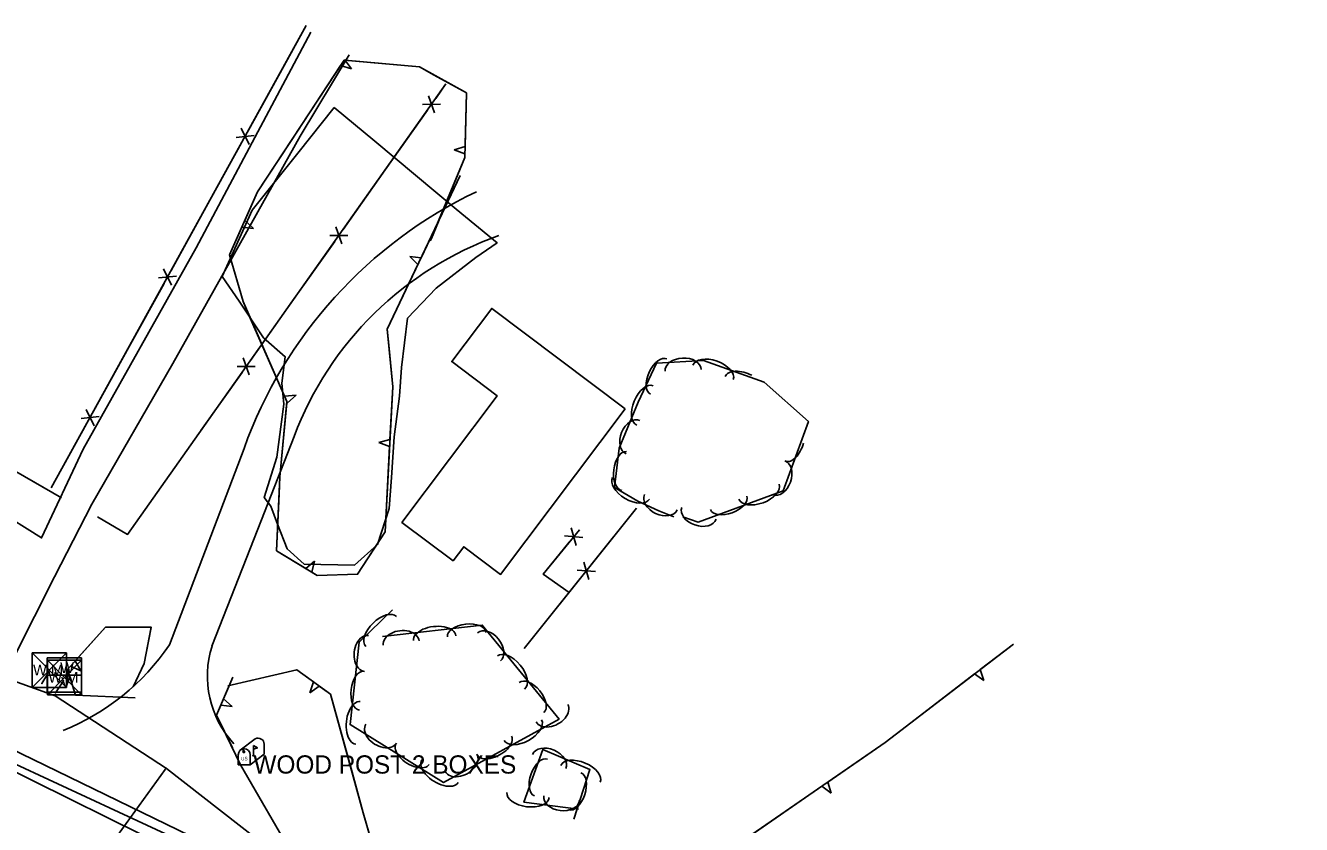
# Model space of a CAD drawing. Extents: x 954793 to 988390, y 1867850 to 1924428.
# Drawn here: x 964423.2 to 964773.1, y 1900700.5 to 1900919.5 of the extents above; entities that cross this region are included whole.
import ezdxf

# ---------------------------------------------------------------- set-up
doc = ezdxf.new("R2010")
doc.units = 0
for name, color, linetype in [('S_BUILDING', 7, 'Continuous'), ('S_DRIVEWAY', 7, 'Continuous'), ('S_FENCE', 7, 'Continuous'), ('S_FIBER_OPTIC_CABLE', 7, 'Continuous'), ('S_MAILBOX', 7, 'Continuous'), ('S_MAILBOX_ANNOT', 7, 'Continuous'), ('S_OBSCURES', 7, 'Continuous'), ('S_TREE', 7, 'Continuous'), ('S_UTL_PT_SYM', 7, 'Continuous'), ('S_WATER_UTILITIES', 7, 'Continuous')]:
    doc.layers.add(name, color=color, linetype=linetype)

msp = doc.modelspace()

# ---------------------------------------------------------------- linework, layer by layer
at = {"layer": 'S_BUILDING'}
msp.add_lwpolyline([(964587.61, 1900814.47), (964553.46, 1900769.08), (964543.35, 1900776.68), (964540.44, 1900772.82), (964526.43, 1900783.35), (964552.53, 1900818.04), (964540.07, 1900827.42), (964551.03, 1900841.99)], close=True, dxfattribs=at)
at = {"layer": 'S_DRIVEWAY'}
for points in [[(964501.46, 1900917.73), (964470.02, 1900858.62), (964439.06, 1900803.44), (964427.61, 1900779.09), (964415.01, 1900786.98), (964408.03, 1900790.26)], [(964414.54, 1900735.61), (964431.15, 1900768.41), (964441.36, 1900788.36), (964463.61, 1900826.91), (964479.18, 1900854.57), (964498.54, 1900889.19), (964511.97, 1900911.54)], [(964474.34, 1900749.37), (964486.93, 1900781.52), (964496.87, 1900806.92)], [(964483.13, 1900803.59), (964462.65, 1900749.74)]]:
    msp.add_lwpolyline(points, dxfattribs=at)
for centre, major_axis, ratio, start_param, end_param in [((964600.34, 1900761.56), (-97.01, -78.14), 0.999418, 4.478485, 5.260538), ((964583.94, 1900774.15), (-41.46, -83.42), 0.99866, 3.94198, 4.813547), ((964411.01, 1900784.53), (42.58, 46.67), 0.985265, 4.255726, 4.857047), ((964499.54, 1900740.8), (11.8, -24.14), 0.981329, 3.938934, 5.008652)]:
    msp.add_ellipse(centre, major_axis=major_axis, ratio=ratio, start_param=start_param, end_param=end_param, dxfattribs=at)
at = {"layer": 'S_FENCE'}
for p, q in [((964532.06, 1900897.93), (964537.03, 1900897.94)), ((964535.37, 1900895.59), (964533.72, 1900900.27)), ((964484.52, 1900886.89), (964482.31, 1900891.38)), ((964480.93, 1900888.87), (964485.9, 1900889.4)), ((964509.97, 1900859.67), (964508.32, 1900864.34)), ((964506.66, 1900862), (964511.63, 1900862.01)), ((964463.26, 1900848.36), (964461.06, 1900852.85)), ((964459.68, 1900850.34), (964464.65, 1900850.87)), ((964484.57, 1900823.74), (964482.91, 1900828.42)), ((964481.26, 1900826.07), (964486.22, 1900826.08)), ((964442.01, 1900809.83), (964439.81, 1900814.32)), ((964438.43, 1900811.81), (964443.4, 1900812.34)), ((964571.01, 1900779.61), (964575.99, 1900779.24)), ((964574.18, 1900777.02), (964572.82, 1900781.83)), ((964576.26, 1900772.47), (964577.67, 1900767.68)), ((964579.46, 1900769.92), (964574.47, 1900770.23))]:
    msp.add_line(p, q, dxfattribs=at)
for points in [[(964430.29, 1900792.81), (964500.18, 1900919.53)], [(964494.04, 1900908.4), (964500.18, 1900919.53)], [(964484.38, 1900890.89), (964494.04, 1900908.4)], [(964442.95, 1900784.84), (964451.2, 1900780.05), (964538.5, 1900903.52)], [(964535.7, 1900899.57), (964538.5, 1900903.52)], [(964521.84, 1900879.97), (964533.39, 1900896.3)], [(964472.79, 1900869.87), (964482.45, 1900887.39)], [(964510.3, 1900863.64), (964521.84, 1900879.97)], [(964463.13, 1900852.36), (964472.79, 1900869.87)], [(964496.44, 1900844.04), (964507.99, 1900860.37)], [(964451.54, 1900831.34), (964461.2, 1900848.85)], [(964484.89, 1900827.71), (964496.44, 1900844.04)], [(964441.88, 1900813.83), (964451.54, 1900831.34)], [(964471.31, 1900808.49), (964482.58, 1900824.44)], [(964430.29, 1900792.81), (964439.95, 1900810.32)], [(964433.12, 1900790.1), (964415.1, 1900800.42), (964399.59, 1900781.83)], [(964433.12, 1900790.1), (964415.76, 1900800.04)], [(964590.69, 1900787.27), (964559.96, 1900748.76)], [(964590.69, 1900787.27), (964578.21, 1900771.64)], [(964442.95, 1900784.84), (964445.41, 1900783.41)], [(964572.24, 1900764.09), (964565.11, 1900769.18), (964575.06, 1900781.33)], [(964574.77, 1900780.97), (964575.06, 1900781.33)], [(964572.24, 1900764.09), (964565.11, 1900769.18), (964572.23, 1900777.88)], [(964575.72, 1900768.51), (964563.25, 1900752.87)], [(964563.25, 1900752.87), (964559.96, 1900748.76)]]:
    msp.add_lwpolyline(points, dxfattribs=at)
at = {"layer": 'S_FIBER_OPTIC_CABLE'}
for p, q in [((964482.14, 1900690.77), (964389.31, 1900735.85)), ((964481.04, 1900688.98), (964388.89, 1900731.66)), ((964475.57, 1900687.67), (964389.43, 1900730.27))]:
    msp.add_line(p, q, dxfattribs=at)
at = {"layer": 'S_MAILBOX'}
for p, q in [((964482.08, 1900720.9), (964486.22, 1900724.01)), ((964488.65, 1900722.54), (964488.65, 1900719.82)), ((964481.53, 1900719.63), (964481.53, 1900716.91)), ((964484.85, 1900716.91), (964488.65, 1900719.82)), ((964484.85, 1900719.63), (964484.85, 1900716.91)), ((964485.7, 1900722.19), (964485.7, 1900719.48)), ((964481.53, 1900716.91), (964484.85, 1900716.91))]:
    msp.add_line(p, q, dxfattribs=at)
for points in [[(964482.71, 1900720.74), (964482.93, 1900720.61), (964482.93, 1900720.22), (964483.24, 1900720.22), (964483.24, 1900720.58), (964483.04, 1900720.83), (964482.71, 1900720.77)], [(964485.7, 1900722.19), (964486.81, 1900721.53), (964485.7, 1900721.18)]]:
    msp.add_lwpolyline(points, dxfattribs=at)
for centre, end in [((964486.99, 1900722.54), 117.5718), ((964483.19, 1900719.63), 180)]:
    msp.add_arc(centre, 1.66, 0, end, dxfattribs=at)
msp.add_ellipse((964485.7, 1900719.48), major_axis=(0.145, 0.132), ratio=0.564646, dxfattribs=at)
at = {"layer": 'S_OBSCURES'}
msp.add_lwpolyline([(964507.86, 1900897.07), (964497.9, 1900884.58), (964485.37, 1900868.89), (964477.09, 1900850.7), (964481.77, 1900843.97), (964488.49, 1900833.92), (964494.43, 1900828.74), (964493.48, 1900821.53), (964494.08, 1900815.77), (964492.14, 1900801.18), (964488.67, 1900790.19), (964490.5, 1900787.8), (964492.28, 1900782.82), (964494.97, 1900776.09), (964499.59, 1900771.89), (964513.39, 1900771.64), (964519.72, 1900777.27), (964522.91, 1900787.18), (964523.54, 1900795.6), (964524.26, 1900806.8), (964525.77, 1900817.94), (964526.32, 1900825.82), (964527.97, 1900839.35), (964535.83, 1900847.56), (964546.66, 1900855.91), (964552.49, 1900859.97), (964541.33, 1900869.24), (964530.17, 1900878.52), (964519.02, 1900887.79)], close=True, dxfattribs=at)
at = {"layer": 'S_TREE'}
for p, q in [((964509.59, 1900908.54), (964512.62, 1900907.68)), ((964512.62, 1900907.68), (964510.67, 1900910.18)), ((964543.72, 1900886.35), (964540.7, 1900885.48)), ((964540.7, 1900885.48), (964543.67, 1900884.38)), ((964485.68, 1900863.93), (964483.36, 1900866.08)), ((964482.56, 1900864.29), (964485.68, 1900863.93)), ((964531.66, 1900855.82), (964528.55, 1900856.25)), ((964528.55, 1900856.25), (964530.82, 1900854.05)), ((964497.4, 1900818.17), (964494.24, 1900817.9)), ((964495.03, 1900816.1), (964497.4, 1900818.17)), ((964523.13, 1900806.06), (964520.09, 1900805.28)), ((964520.09, 1900805.28), (964523.03, 1900804.1)), ((964502.47, 1900772.75), (964500.05, 1900770.71)), ((964501.73, 1900769.69), (964502.47, 1900772.75)), ((964435.54, 1900743.96), (964438.4, 1900742.65)), ((964438.4, 1900742.65), (964436.86, 1900745.42)), ((964683.42, 1900741.8), (964686, 1900740)), ((964686, 1900740), (964684.98, 1900743)), ((964502.14, 1900739.63), (964501.15, 1900736.65)), ((964501.15, 1900736.65), (964503.74, 1900738.48)), ((964476.75, 1900733.2), (964479.88, 1900732.88)), ((964479.88, 1900732.88), (964477.53, 1900735)), ((964644.06, 1900709.08), (964643.19, 1900712.13)), ((964641.58, 1900711.01), (964644.06, 1900709.08))]:
    msp.add_line(p, q, dxfattribs=at)
for points in [[(964542.37, 1900878.39), (964522.39, 1900836.28), (964523.9, 1900820.54), (964521.79, 1900780.75), (964514.25, 1900769.14), (964503.21, 1900768.8), (964492.04, 1900775.55), (964492.94, 1900795.85), (964494.87, 1900816.48), (964482.86, 1900843.88), (964479.18, 1900856.68), (964486.84, 1900873.91), (964510.59, 1900910.05), (964531.22, 1900908.17), (964544.11, 1900901.07), (964543.64, 1900883.35), (964534.19, 1900860.47)], [(964495.86, 1900887.65), (964509.59, 1900908.54)], [(964510.74, 1900910.04), (964531.22, 1900908.17), (964535.1, 1900906.03)], [(964535.1, 1900906.03), (964544.11, 1900901.07), (964543.72, 1900886.35)], [(964483.36, 1900866.08), (964486.84, 1900873.91), (964495.86, 1900887.65)], [(964543.67, 1900884.38), (964543.64, 1900883.35), (964534.49, 1900861.2)], [(964542.37, 1900878.39), (964531.66, 1900855.82)], [(964484.2, 1900840.8), (964482.86, 1900843.88), (964479.18, 1900856.68), (964482.56, 1900864.29)], [(964534.49, 1900861.2), (964534.19, 1900860.47)], [(964530.82, 1900854.05), (964522.39, 1900836.28), (964522.9, 1900830.99)], [(964494.24, 1900817.9), (964484.2, 1900840.8)], [(964522.9, 1900830.99), (964523.9, 1900820.54), (964523.13, 1900806.06)], [(964601, 1900784.82), (964596.85, 1900786.49), (964591.07, 1900789.17), (964584.66, 1900792.91), (964585.98, 1900803.7), (964591.16, 1900816.26), (964596.22, 1900827.02), (964609.1, 1900827.67), (964625.73, 1900821.77), (964637.85, 1900810.97), (964630.99, 1900791.96), (964607.67, 1900783.37), (964603.47, 1900784.82)], [(964492.74, 1900791.16), (964492.94, 1900795.85), (964494.83, 1900816.07)], [(964523.03, 1900804.1), (964521.79, 1900780.75), (964520.91, 1900779.39)], [(964500.05, 1900770.71), (964492.04, 1900775.55), (964492.74, 1900791.16)], [(964520.91, 1900779.39), (964514.25, 1900769.14), (964503.21, 1900768.8), (964501.73, 1900769.69)], [(964521.05, 1900752.08), (964548.46, 1900755.19), (964569.52, 1900729.42), (964537.78, 1900712.04), (964512.2, 1900727.93), (964514.65, 1900750.47), (964523.79, 1900759.35)], [(964453.28, 1900735.24), (964436.96, 1900735.97), (964434.71, 1900743.04), (964445.18, 1900754.63), (964457.69, 1900754.6), (964455.74, 1900744.64), (964452.75, 1900738.28)], [(964436.86, 1900745.42), (964445.18, 1900754.63), (964457.69, 1900754.6), (964457.68, 1900754.53)], [(964457.68, 1900754.53), (964455.74, 1900744.64), (964452.75, 1900738.28)], [(964773.05, 1900666.58), (964744.57, 1900646.52), (964725.6, 1900649.05), (964710.57, 1900666.38), (964700.3, 1900676.13), (964691.03, 1900680.68), (964665.4, 1900668.82), (964619.49, 1900640.89), (964600.99, 1900650.38), (964604.11, 1900685.16), (964658.89, 1900722.96), (964694.06, 1900749.97)], [(964684.98, 1900743), (964694.06, 1900749.97)], [(964453.28, 1900735.24), (964436.96, 1900735.97), (964434.71, 1900743.04), (964435.54, 1900743.96)], [(964478.73, 1900738.52), (964497.58, 1900742.94), (964506.87, 1900736.21), (964515.83, 1900703.76), (964522.2, 1900681.57), (964516.72, 1900667.69), (964496.84, 1900691.48), (964482.15, 1900716.91), (964475.61, 1900730.53), (964480.06, 1900740.88)], [(964477.53, 1900735), (964480.06, 1900740.88)], [(964478.73, 1900738.52), (964497.58, 1900742.94), (964502.14, 1900739.63)], [(964663.6, 1900726.57), (964683.42, 1900741.8)], [(964503.74, 1900738.48), (964506.87, 1900736.21), (964512.49, 1900715.84)], [(964479.94, 1900721.5), (964475.61, 1900730.53), (964476.75, 1900733.2)], [(964643.19, 1900712.13), (964658.89, 1900722.96), (964663.6, 1900726.57)], [(964574.86, 1900704.76), (964559.86, 1900706.62), (964565.08, 1900721.1), (964577.98, 1900715.6), (964573.55, 1900702.02)], [(964512.49, 1900715.84), (964515.83, 1900703.76), (964519.27, 1900691.77)], [(964621, 1900696.81), (964641.58, 1900711.01)]]:
    msp.add_lwpolyline(points, dxfattribs=at)
for centre, major_axis, ratio, start_param, end_param in [((964596.82, 1900823.31), (-2.27, -4.84), 0.540699, 3.141593, 6.283185), ((964603.52, 1900825), (-4.95, -0.25), 0.685311, 3.141593, 6.283185), ((964611.74, 1900824.48), (-5.53, 1.96), 0.55008, 3.141593, 6.283185), ((964620.1, 1900821.51), (-5.04, 1.79), 0.540699, 4.437811, 6.283185), ((964593.09, 1900815.37), (-2.24, -5.42), 0.55008, 3.141593, 6.283185), ((964589.8, 1900806.72), (-1.89, -4.58), 0.685311, 3.141593, 6.283185), ((964587.35, 1900797.43), (-0.65, -5.31), 0.540699, 3.141593, 6.283185), ((964633.49, 1900805.13), (1.81, 5.03), 0.540699, 3.141593, 4.882628), ((964629.74, 1900795.53), (1.68, 4.66), 0.685311, 3.141593, 6.283185), ((964589.23, 1900792.7), (5.07, -2.96), 0.55008, 3.141593, 6.283185), ((964624.32, 1900791.76), (5.51, 2.03), 0.55008, 3.141593, 6.283185), ((964597.41, 1900788.85), (4.49, -2.09), 0.685311, 3.141593, 6.283185), ((964616, 1900788.7), (5.02, 1.85), 0.540699, 3.141593, 6.283185), ((964607.84, 1900785.84), (4.69, -1.61), 0.685311, 3.141593, 6.283185), ((964520.75, 1900753.44), (-4.21, -4.09), 0.549313, 3.141593, 6.283185), ((964526.24, 1900750.28), (-4.92, -0.56), 0.685058, 3.141633, 6.283226), ((964535.41, 1900751.58), (-5.83, -0.66), 0.549877, 3.141617, 6.28321), ((964544.22, 1900752.58), (-5.31, -0.6), 0.5405, 3.141617, 6.283209), ((964550.28, 1900749.2), (-3.14, 3.84), 0.685034, 3.141593, 6.283185), ((964516.71, 1900747.42), (-0.54, -4.93), 0.68424, 3.141719, 6.283312), ((964556.34, 1900742.19), (-3.71, 4.54), 0.549858, 3.141593, 6.283185), ((964515.34, 1900737.21), (-0.58, -5.32), 0.539855, 3.141668, 6.28326), ((964561.95, 1900735.33), (-3.38, 4.14), 0.540481, 3.141593, 6.283185), ((964514.38, 1900728.39), (-0.63, -5.83), 0.54922, 3.14167, 6.283263), ((964567.55, 1900731.06), (4.34, 2.39), 0.685344, 3.138968, 6.280561), ((964520.73, 1900725.44), (4.2, -2.61), 0.686026, 3.142228, 6.283821), ((964559.57, 1900726.39), (5.14, 2.82), 0.550107, 3.139991, 6.281583), ((964529.33, 1900719.79), (4.54, -2.82), 0.541264, 3.141968, 6.283561), ((964551.8, 1900722.13), (4.68, 2.57), 0.540726, 3.140041, 6.281634), ((964542.65, 1900717.42), (4.34, 2.39), 0.685344, 3.138968, 6.280561), ((964564.56, 1900713.4), (-1.81, -5.03), 0.540699, 3.141593, 6.283185), ((964566.79, 1900717.78), (-4.56, 1.94), 0.685311, 3.141593, 6.283185), ((964536.86, 1900715.12), (4.98, -3.09), 0.550654, 3.14198, 6.283573), ((964575.41, 1900714.39), (-5.4, 2.3), 0.55008, 3.141593, 6.283185), ((964573.8, 1900709.62), (1.66, 5.08), 0.540699, 3.141593, 6.283185), ((964561.01, 1900708.61), (5.82, -0.72), 0.55008, 3.141593, 6.283185), ((964570.23, 1900707.73), (4.92, -0.61), 0.685311, 3.141593, 6.283185)]:
    msp.add_ellipse(centre, major_axis=major_axis, ratio=ratio, start_param=start_param, end_param=end_param, dxfattribs=at)
at = {"layer": 'S_UTL_PT_SYM'}
for points in [[(964429.6, 1900742.37), (964429.6, 1900742.42), (964429.6, 1900742.37), (964429.55, 1900742.37), (964429.6, 1900742.37), (964429.6, 1900742.32), (964429.6, 1900742.37), (964429.65, 1900742.37)], [(964433.66, 1900739.89), (964433.66, 1900739.94), (964433.66, 1900739.89), (964433.61, 1900739.89), (964433.66, 1900739.89), (964433.66, 1900739.84), (964433.66, 1900739.89), (964433.71, 1900739.89)], [(964427.7, 1900739.18), (964427.7, 1900739.23), (964427.7, 1900739.18), (964427.65, 1900739.18), (964427.7, 1900739.18), (964427.7, 1900739.13), (964427.7, 1900739.18), (964427.75, 1900739.18)], [(964431.44, 1900736.61), (964431.44, 1900736.66), (964431.44, 1900736.61), (964431.39, 1900736.61), (964431.44, 1900736.61), (964431.44, 1900736.56), (964431.44, 1900736.61), (964431.49, 1900736.61)], [(964431.34, 1900735.79), (964431.34, 1900735.84), (964431.34, 1900735.79), (964431.29, 1900735.79), (964431.34, 1900735.79), (964431.34, 1900735.74), (964431.34, 1900735.79), (964431.39, 1900735.79)], [(964461.47, 1900715.59), (964461.47, 1900715.64), (964461.47, 1900715.59), (964461.42, 1900715.59), (964461.47, 1900715.59), (964461.47, 1900715.54), (964461.47, 1900715.59), (964461.52, 1900715.59)], [(964461.83, 1900715.92), (964461.83, 1900715.97), (964461.83, 1900715.92), (964461.78, 1900715.92), (964461.83, 1900715.92), (964461.83, 1900715.87), (964461.83, 1900715.92), (964461.88, 1900715.92)]]:
    msp.add_lwpolyline(points, dxfattribs=at)
at = {"layer": 'S_WATER_UTILITIES'}
for p, q in [((964431.34, 1900735.79), (964358.93, 1900761.64)), ((964425.08, 1900747.6), (964434.42, 1900747.6)), ((964425.08, 1900747.6), (964425.08, 1900738.11)), ((964425.08, 1900747.6), (964434.42, 1900738.11)), ((964434.42, 1900747.6), (964425.08, 1900738.11)), ((964434.42, 1900747.6), (964434.42, 1900738.11)), ((964429.16, 1900746.18), (964438.58, 1900746.18)), ((964429.16, 1900736.76), (964429.16, 1900746.18)), ((964429.26, 1900745.59), (964438.6, 1900745.59)), ((964429.26, 1900745.59), (964429.26, 1900736.1)), ((964429.26, 1900745.59), (964438.6, 1900736.1)), ((964438.6, 1900745.59), (964429.26, 1900736.1)), ((964438.58, 1900746.18), (964438.58, 1900736.76)), ((964438.6, 1900745.59), (964438.6, 1900736.1)), ((964429.6, 1900742.37), (964427.7, 1900739.18)), ((964429.16, 1900741.49), (964438.58, 1900741.49)), ((964425.08, 1900738.11), (964434.42, 1900738.11)), ((964438.58, 1900736.76), (964429.16, 1900736.76)), ((964431.44, 1900736.61), (964433.66, 1900739.89)), ((964429.26, 1900736.1), (964438.6, 1900736.1)), ((964461.83, 1900715.92), (964431.34, 1900735.79)), ((964461.47, 1900715.59), (964405.78, 1900638.54)), ((964506.62, 1900681.08), (964461.83, 1900715.92))]:
    msp.add_line(p, q, dxfattribs=at)

# ---------------------------------------------------------------- texts
at = {"layer": 'S_MAILBOX'}
msp.add_text('US', height=0.96, rotation=360, dxfattribs=at).set_placement((964482.29, 1900718.11))
at = {"layer": 'S_MAILBOX_ANNOT'}
msp.add_text('WOOD POST 2 BOXES', height=5, dxfattribs=at).set_placement((964485.7, 1900714.48))
at = {"layer": 'S_WATER_UTILITIES'}
for s, p in [('W M', (964425.28, 1900741.37)), ('W', (964432.71, 1900742.02)), ('W M', (964429.47, 1900739.36)), ('V', (964432.95, 1900737.96))]:
    msp.add_text(s, height=3, rotation=360, dxfattribs=at).set_placement(p)

doc.saveas('drawing.dxf')
